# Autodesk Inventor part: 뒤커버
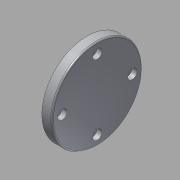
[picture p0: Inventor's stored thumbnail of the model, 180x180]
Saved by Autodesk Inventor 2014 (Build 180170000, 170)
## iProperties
Created: 2015-09
Part Number: 뒤커버
Material: 알루미늄 6061
Document SubType Name: Modeling
Designer: mduedu
Density: 2.71 g/cm^3
Mass: 54.0417 g
Surface Area: 84.9688 cm^2
Volume: 19.9416 cm^3
Appearance: Aluminum - Flat
Author: mduedu
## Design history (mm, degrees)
sketch "스케치1"
  geometry: L1 (-15.5, 47)-(-15.5, 78); L2 (-15.5, 78)-(-22.5, 78); L3 (-22.5, 78)-(-22.5, 67); L4 (-25.5, 67)-(-25.5, 47); L5 (-79.5, 39.5)-(-79.5, 54.5) reference; L6 (48.5, 54.5)-(48.5, 39.5) reference; L7 (-79.5, 47)-(48.5, 47); L8 (-22.5, 67)-(-25.5, 67); L9 (-25.5, 47)-(-15.5, 47); 1 further point
  constraints: 14 end point, 4 midpoint, 3 parallel, 1 collinear, 1 point on line, 1 vertical
  dimensions: "d6" = 62 diameter of L2 L7; "d7" = 7 distance of L1.end L2.end; "d8" = 40 diameter of L3.end L7; "d32" = 10 distance between parallel lines of L1 L4
revolve "회전1" sketch "스케치1" stored, may be unused: angle "d4" = 90 deg
sketch "스케치4"
  geometry: C1 r 31 at (0, 0) reference; 2 further points
  constraints: 1 coincident
hole "구멍3" sketch "스케치4" at (0, 0) diameter "d33" = 33; stored, may be unused: countersink angle "d37" = 90 deg, drill point angle "d39" = 0 deg; dims "d34" = 6, "d35" = 4, "d36" = 2, "d38" = 5
fillet "모깎기4" dims "d40" = 1
chamfer "모따기2" distance "d41" = 1; stored, may be unused: second distance "d42" = 2, angle "d43" = 45 deg
sketch "스케치5" dims "d44" = 48
  geometry: C1 r 31 at (0, 0) reference; 6 further points
  constraints: 2 vertical alignment, 1 coincident, 7 other
  dimensions: "d47" = 360 deg dimension on C1.centre point (0, -24) (derived)
sketch "스케치6"
  geometry: 4 further points
hole "구멍4" sketch "스케치6" at (24, 0), (0, 24), (-24, 0), (0, -24) diameter "d49" = 3.4; stored, may be unused: countersink angle "d53" = 90 deg, drill point angle "d55" = 0 deg; dims "d50" = 6, "d51" = 6.5, "d52" = 3.4, "d54" = 8
node "솔리드1"
node "참조1"
node "참조2"
